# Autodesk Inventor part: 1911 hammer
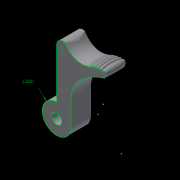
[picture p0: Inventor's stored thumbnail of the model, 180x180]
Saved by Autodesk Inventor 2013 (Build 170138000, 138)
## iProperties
Created: 2013-01
Part Number: 1911 hammer
Material: Generic
Document SubType Name: Modeling
Designer: John
Density: 1 g/cm^3
Author: John
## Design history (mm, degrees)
sketch "Sketch1"
  geometry: L1 (5.639, 5.854)-(5.639, 9.652) reference; L2 (0, 8.128)-(0, 25.044); C1 r 2 at (0, 0); A1 r 8.128 centre (0, 0) between (0, 8.128) and (5.639, 5.854) reference; A2 r 12.192 centre (18.288, 13.97) between (18.288, 26.162) and (12.61, 24.759) reference; A3 r 1.524 centre (18.288, 24.638) between (18.723, 23.177) and (18.288, 26.162) reference; A4 r 6.35 centre (9.652, 30.378) between (4.572, 26.568) and (12.61, 24.759) reference; A5 r 2.54 centre (2.54, 25.044) between (4.572, 26.568) and (0, 25.044) reference; A6 r 10.668 centre (16.307, 9.652) between (8.671, 17.102) and (5.639, 9.652) reference; A7 r 23.368 centre (25.397, 0.783) between (18.723, 23.177) and (8.671, 17.102); 1 further point
  constraints: 14 point on circle, 8 centre point, 7 tangent, 4 end point, 2 coincident, 1 parallel, 1 vertical, 6 other
  dimensions: "d13" = 4.0005 diameter of C1; "d55" = 8.128 radius of A1 (derived)
extrude "Extrusion1" new body sketch "Sketch1" stored distance "d14" = 7.8486; taper "d15" = 0 deg
workplane "Work Plane2"
sketch "Sketch3"
  geometry: L1 (-7.849, -6.902)-(-7.849, -6.164); L2 (-7.849, -6.164)-(0, -6.164); L3 (0, -6.164)-(0, -6.902); A1 r 14.224 centre (-3.924, -20.574) between (0, -6.902) and (-7.849, -6.902); 1 further point
  constraints: 6 end point, 2 point on circle, 1 centre point
sketch "Sketch4"
  geometry: L1 (4.572, 26.568)-(1.36, 30.85); L2 (19.725, 24.13)-(17.507, 17.856); A1 r 6.35 centre (9.652, 30.378) between (4.572, 26.568) and (12.61, 24.759) reference; A2 r 12.192 centre (18.288, 13.97) between (18.288, 26.162) and (12.61, 24.759) reference; A3 r 1.524 centre (18.288, 24.638) between (19.725, 24.13) and (18.288, 26.162); 1 further point
  constraints: 4 end point, 3 point on circle, 1 centre point, 1 tangent
sweep "Sweep1" sketch "Sketch3", "Sketch4" dims "d18" = 0
sketch "Sketch6"
  geometry: L1 (18.288, 13.97)-(30.48, 13.97); L2 (18.288, 26.162)-(17.993, 25.65); L3 (16.915, 26.084)-(16.674, 25.542); L4 (15.599, 25.862)-(15.415, 25.295); L5 (14.28, 25.485)-(14.156, 24.899); L6 (13.064, 25.081)-(12.991, 24.384); L7 (12.085, 24.606)-(12.718, 24.241); L8 (13.403, 25.141)-(13.883, 24.792); L9 (14.735, 25.633)-(15.179, 25.233); L10 (15.952, 25.936)-(16.352, 25.492); L11 (17.343, 26.125)-(17.696, 25.639); L12 (18.813, 12.007)-(31.194, 15.316); A1 r 1.524 centre (18.288, 24.638) between (19.725, 24.13) and (18.288, 26.162) reference; A2 r 6.264 centre (9.652, 30.378) between (12.085, 24.606) and (12.559, 24.829); A3 r 12.278 centre (18.288, 13.97) between (13.064, 25.081) and (12.559, 24.829); A4 r 12.192 centre (18.288, 13.97) between (14.28, 25.485) and (13.403, 25.141); A5 r 12.192 centre (18.288, 13.97) between (15.599, 25.862) and (14.735, 25.633); A6 r 12.192 centre (18.288, 13.97) between (18.288, 26.162) and (17.343, 26.125); A7 r 12.192 centre (18.288, 13.97) between (16.915, 26.084) and (15.952, 25.936); A8 r 11.684 centre (18.288, 13.97) between (17.993, 25.65) and (17.696, 25.639); A9 r 11.684 centre (18.288, 13.97) between (16.674, 25.542) and (16.352, 25.492); A10 r 11.684 centre (18.288, 13.97) between (15.415, 25.295) and (15.179, 25.233); A11 r 11.684 centre (18.288, 13.97) between (14.156, 24.899) and (13.883, 24.792); A12 r 11.684 centre (18.288, 13.97) between (12.991, 24.384) and (12.718, 24.241); 2 further points
  constraints: 24 end point, 23 point on circle, 11 centre point, 2 coincident, 1 horizontal
revolve "Revolution1" sketch "Sketch6" stored, may be unused: angle "d54" = 90 deg
sketch "Sketch7"
  geometry: L1 (5.639, 5.854)-(5.639, 9.652) reference; L2 (0, 8.128)-(0, 5.639); L3 (5.639, 5.854)-(5.639, 0); A1 r 8.128 centre (0, 0) between (0, 8.128) and (5.639, 5.854) reference; A2 r 5.639 centre (0, 0) between (0, 5.639) and (5.639, 0)
  constraints: 4 end point, 2 point on circle, 1 centre point, 1 coincident, 1 collinear, 1 parallel, 1 tangent
extrude "Extrusion2" cut sketch "Sketch7" distance "d57" = 25.4; taper "d58" = 0 deg
sketch "Sketch8"
  geometry: L1 (0, 25.044)-(0, 5.639) reference; L2 (5.639, 0)-(5.639, 9.652) reference; L3 (18.813, 23.207)-(19.204, 24.314) reference; L4 (4.13, 26.237)-(3.182, 27.502) reference; C1 r 2 at (0, 0) reference; A1 r 5.639 centre (0, 0) between (0, 5.639) and (5.639, 0) reference; A2 r 10.668 centre (16.307, 9.652) between (8.671, 17.102) and (5.639, 9.652) reference; A3 r 23.368 centre (25.397, 0.783) between (18.723, 23.177) and (8.671, 17.102) reference; A4 r 1.524 centre (18.288, 24.638) between (18.723, 23.177) and (18.813, 23.207) reference; A5 r 0.972 centre (18.288, 24.638) between (19.204, 24.314) and (18.428, 25.6) reference; A6 r 11.64 centre (18.288, 13.97) between (17.489, 25.582) and (17.059, 25.545) reference; A7 r 11.64 centre (18.288, 13.97) between (16.095, 25.402) and (15.741, 25.328) reference; A8 r 11.64 centre (18.288, 13.97) between (14.877, 25.099) and (14.423, 24.95) reference; A9 r 11.64 centre (18.288, 13.97) between (13.548, 24.601) and (13.199, 24.438) reference; A10 r 6.902 centre (9.652, 30.378) between (4.13, 26.237) and (12.314, 24.01) reference; A11 r 2.54 centre (2.54, 25.044) between (3.182, 27.502) and (0, 25.044) reference; 10 further points
  constraints: 15 other
  dimensions: "d59" = 5.6388 radius of A1 (derived)
body "Solid1"
